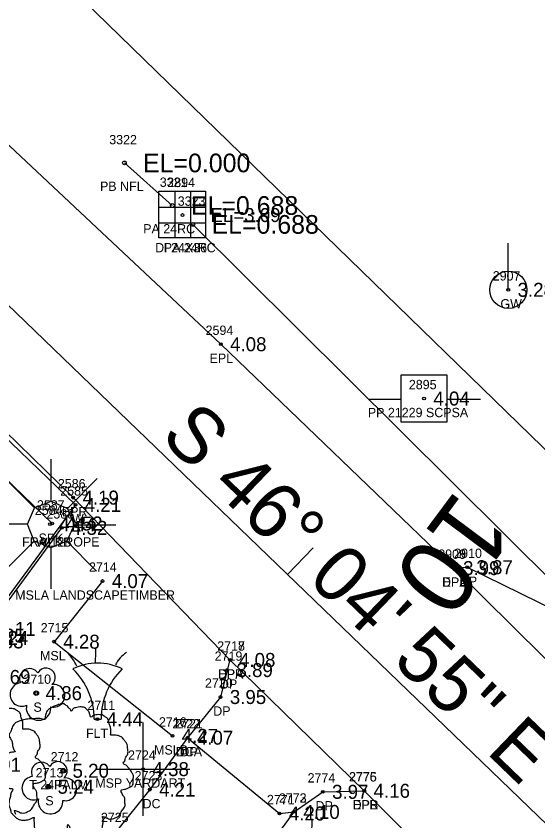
# Model space of a CAD drawing. Extents: x 2608598 to 2610682, y 641451 to 643526.
# Drawn here: x 2610142.2 to 2610198.2, y 642038.3 to 642124.7 of the extents above; entities that cross this region are included whole.
import ezdxf

# ---------------------------------------------------------------- set-up
doc = ezdxf.new("R2010")
doc.units = 0
for name, color, linetype in [('RD_EX_BldgApp', 7, 'Continuous'), ('RD_EX_BldgApp_txCode', 7, 'Continuous'), ('RD_EX_Conc', 7, 'Continuous'), ('RD_EX_Conc_txCode', 7, 'Continuous'), ('RD_EX_DR_Inlet', 7, 'Continuous'), ('RD_EX_DR_Inlet_txCode', 7, 'Continuous'), ('RD_EX_DR_Pipe', 7, 'Continuous'), ('RD_EX_DR_Pipe_txCode', 7, 'Continuous'), ('RD_EX_Driveway', 7, 'Continuous'), ('RD_EX_Driveway_txCode', 7, 'Continuous'), ('RD_EX_Fence_Other', 7, 'Continuous'), ('RD_EX_Fence_Other_txCode', 7, 'Continuous'), ('RD_EX_Misc', 7, 'Continuous'), ('RD_EX_Misc_txCode', 7, 'Continuous'), ('RD_EX_Road', 7, 'Continuous'), ('RD_EX_Road_txCode', 7, 'Continuous'), ('RD_EX_TX_BldgApp_ELEV', 7, 'Continuous'), ('RD_EX_TX_Conc_ELEV', 7, 'Continuous'), ('RD_EX_TX_DR_Inlet_ELEV', 7, 'Continuous'), ('RD_EX_TX_Driveway_ELEV', 7, 'Continuous'), ('RD_EX_TX_Fence_Other_ELEV', 7, 'Continuous'), ('RD_EX_TX_Misc_ELEV', 7, 'Continuous'), ('RD_EX_TX_Road_ELEV', 7, 'Continuous'), ('RD_EX_TX_UT_ELEV', 7, 'Continuous'), ('RD_EX_TX_VEG_ELEV', 7, 'Continuous'), ('RD_EX_UT', 7, 'Continuous'), ('RD_EX_UT_txCode', 7, 'Continuous'), ('RD_EX_VEG', 7, 'Continuous'), ('RD_EX_VEG_txCode', 7, 'Continuous'), ('RD_HC_Cl', 7, 'Continuous'), ('RD_HC_Data', 7, 'Continuous'), ('RD_HC_Data_Tic', 7, 'Continuous'), ('RD_HC_Survey_ELEV', 7, 'Continuous'), ('RD_HC_TX_Sta50', 7, 'Continuous'), ('RD_SMD_Locator', 7, 'Continuous'), ('RD_TX_Pipe_ElevEX', 7, 'Continuous')]:
    doc.layers.add(name, color=color, linetype=linetype)

msp = doc.modelspace()

# ---------------------------------------------------------------- linework, layer by layer
at = {"layer": 'RD_EX_BldgApp'}
for p, q in [((2610145.949, 642072.643), (2610145.949, 642077.152)), ((2610144.161, 642071.945), (2610140.978, 642075.127)), ((2610147.699, 642071.873), (2610150.895, 642075.069)), ((2610143.418, 642070.181), (2610138.896, 642070.181)), ((2610148.424, 642070.099), (2610152.92, 642070.099)), ((2610144.137, 642068.369), (2610141.019, 642065.251)), ((2610147.646, 642068.344), (2610150.837, 642065.153)), ((2610145.908, 642067.637), (2610145.908, 642063.227)), ((2610150.576, 642049.272), (2610151.326, 642049.272))]:
    msp.add_line(p, q, dxfattribs=at)
msp.add_lwpolyline([(2610134.705, 642085.572), (2610148.567, 642072.254), (2610138.223, 642058.218)], dxfattribs=at)
msp.add_lwpolyline([(2610144.161, 642071.945), (2610145.949, 642072.643), (2610147.699, 642071.873), (2610148.424, 642070.099), (2610147.646, 642068.344), (2610145.908, 642067.637), (2610144.137, 642068.369), (2610143.418, 642070.181)], close=True, dxfattribs=at)
for centre, radius, start, end in [((2610144.258, 642052.915), 4.895, 24.32791, 46.26654), ((2610112.869, 642056.61), 37.876, 358.06712, 0.27154), ((2610155.839, 642053.665), 3.283, 123.29064, 154.48862), ((2610150.951, 642049.272), 5.997, 63.77943, 116.22057), ((2610143.076, 642049.272), 7.5, 0, 45.83662), ((2610158.826, 642049.272), 7.5, 134.16338, 180), ((2610136.107, 642038.394), 37.876, 358.06712, 0.27154)]:
    msp.add_arc(centre, radius, start, end, dxfattribs=at)
at = {"layer": 'RD_EX_Conc'}
for points in [[(2610160.612, 642047.272), (2610156.554, 642041.695), (2610152.931, 642037.213), (2610150.731, 642035.233), (2610148.01, 642033.912), (2610141.177, 642033.459), (2610141.177, 642033.459), (2610137.988, 642033.476), (2610134.44, 642032.913), (2610131.048, 642029.279), (2610128.16, 642026.009), (2610122.885, 642018.814), (2610128.446, 642014.737), (2610133.488, 642011.041), (2610133.129, 642010.552)], [(2610097.632, 641937.698), (2610098.418, 641937.114), (2610146.498, 642001.846), (2610145.188, 642002.764), (2610160.492, 642023.462), (2610172.047, 642039.304)]]:
    msp.add_lwpolyline(points, dxfattribs=at)
at = {"layer": 'RD_EX_DR_Inlet'}
for p, q in [((2610159.228, 642105.905), (2610159.228, 642100.905)), ((2610160.928, 642105.905), (2610160.928, 642100.905)), ((2610157.528, 642104.205), (2610162.528, 642104.205)), ((2610157.528, 642102.505), (2610162.528, 642102.505))]:
    msp.add_line(p, q, dxfattribs=at)
msp.add_lwpolyline([(2610157.528, 642100.905), (2610157.528, 642105.905), (2610162.528, 642105.905), (2610162.528, 642100.905)], close=True, dxfattribs=at)
at = {"layer": 'RD_EX_DR_Pipe'}
for p, q in [((2610158.972, 642104.373), (2610153.828, 642108.939)), ((2610161.182, 642102.345), (2610218.859, 642045.058))]:
    msp.add_line(p, q, dxfattribs=at)
at = {"layer": 'RD_EX_Driveway'}
for points in [[(2610189.201, 642065.464), (2610190.633, 642065.558), (2610206.029, 642058.003), (2610212.058, 642057.248), (2610216.962, 642059.651), (2610226.196, 642070.204), (2610231.836, 642077.34), (2610253.985, 642109.297), (2610264.823, 642124.673)], [(2610165.14, 642055.61), (2610164.867, 642054.527), (2610164.148, 642051.634), (2610160.612, 642047.272), (2610170.483, 642039.135), (2610172.047, 642039.304), (2610175.131, 642041.462), (2610179.59, 642041.571)]]:
    msp.add_lwpolyline(points, dxfattribs=at)
at = {"layer": 'RD_EX_Fence_Other'}
for points in [[(2610132.58, 642142.761), (2610200.01, 642077.228), (2610202.789, 642080.045), (2610213.517, 642069.87), (2610210.469, 642066.294), (2610214.959, 642062.541)], [(2610147.084, 642069.782), (2610125.734, 642040.697), (2610098.694, 642003.858), (2610084.195, 641984.008), (2610080.523, 641986.54)]]:
    msp.add_lwpolyline(points, dxfattribs=at)
at = {"layer": 'RD_EX_Misc'}
for p, q in [((2610155.847, 642038.901), (2610155.847, 642048.901)), ((2610150.847, 642043.901), (2610160.847, 642043.901))]:
    msp.add_line(p, q, dxfattribs=at)
for points in [[(2610099.903, 642104.401), (2610102.737, 642104.088), (2610106.788, 642103.479), (2610109.503, 642102.419), (2610114.982, 642099.42), (2610118.245, 642096.797), (2610132.484, 642083.3), (2610146.063, 642070.249)], [(2610151.474, 642064.076), (2610146.269, 642057.572), (2610158.983, 642047.463)]]:
    msp.add_lwpolyline(points, dxfattribs=at)
at = {"layer": 'RD_EX_Road'}
for points in [[(2609576.606, 642656.063), (2609590.876, 642642.238), (2609605.189, 642628.776), (2609627.581, 642607.088), (2609646.03, 642589.107), (2609702.182, 642534.044), (2609780.351, 642458.947), (2609858.794, 642382.828), (2609938.323, 642306.422), (2610008.617, 642239.319), (2610086.297, 642162.544), (2610164.179, 642089.488), (2610189.201, 642065.464), (2610214.781, 642040.191), (2610225.859, 642030.159), (2610226.316, 642028.389), (2610235.43, 642019.753), (2610260.227, 641995.633), (2610272.389, 641983.247)], [(2609979.125, 642234.193), (2609992.401, 642221.664), (2610004.858, 642210.013), (2610027.001, 642188.802), (2610067.643, 642149.145), (2610070.798, 642146.186), (2610073.957, 642143.053), (2610116.512, 642103.007), (2610119.683, 642100.064), (2610135.088, 642085.919), (2610148.333, 642073.03), (2610165.14, 642055.61), (2610179.59, 642041.571), (2610196.49, 642024.706), (2610209.861, 642011.422), (2610228.388, 641994.056), (2610252.927, 641970.076), (2610256.351, 641966.743)]]:
    msp.add_lwpolyline(points, dxfattribs=at)
at = {"layer": 'RD_EX_UT'}
for p, q in [((2610195.056, 642095.325), (2610195.056, 642100.325)), ((2610188.498, 642086.169), (2610183.498, 642086.169)), ((2610183.498, 642086.169), (2610183.498, 642081.169)), ((2610188.498, 642081.169), (2610188.498, 642086.169)), ((2610180.067, 642083.606), (2610183.536, 642083.606)), ((2610188.427, 642083.606), (2610192.067, 642083.606)), ((2610183.498, 642081.169), (2610188.498, 642081.169))]:
    msp.add_line(p, q, dxfattribs=at)
msp.add_circle((2610195.056, 642095.325), 1.999, dxfattribs=at)
at = {"layer": 'RD_EX_VEG'}
for centre, radius in [((2610144.364, 642052.049), 0.25), ((2610147.256, 642043.722), 0.25), ((2610147.244, 642043.703), 0.0001), ((2610145.642, 642042.006), 0.25)]:
    msp.add_circle(centre, radius, dxfattribs=at)
for centre, radius, start, end in [((2610143.643, 642053.596), 1.084, 34.97629, 204.75602), ((2610145.409, 642053.751), 0.995, 308.76261, 152.04674), ((2610142.8, 642051.893), 1.257, 96.45179, 294.73401), ((2610146.204, 642051.77), 1.218, 256.56668, 98.10463), ((2610144.609, 642050.453), 1.318, 166.88266, 5.75893), ((2610144.921, 642043.553), 1.084, 34.97629, 204.75602), ((2610146.687, 642043.708), 0.995, 308.76261, 152.04674), ((2610144.078, 642041.85), 1.257, 96.45179, 294.73401), ((2610147.482, 642041.727), 1.218, 256.56668, 98.10463), ((2610145.888, 642040.41), 1.318, 166.88266, 5.75893)]:
    msp.add_arc(centre, radius, start, end, dxfattribs=at)
for points in [[(2610142.172, 642039.041), (2610142.097, 642039.216), (2610142.047, 642039.466), (2610142.122, 642039.441), (2610142.297, 642039.391), (2610142.572, 642039.266), (2610142.797, 642039.191), (2610143.121, 642039.216), (2610143.396, 642039.316), (2610143.846, 642039.591), (2610144.121, 642040.066), (2610144.396, 642040.466), (2610144.471, 642040.791), (2610144.421, 642041.016), (2610144.396, 642041.515), (2610144.196, 642041.765), (2610144.146, 642041.89), (2610144.046, 642042.29), (2610144.121, 642042.34), (2610144.396, 642042.39), (2610144.771, 642042.515), (2610145.046, 642042.64), (2610145.271, 642042.815), (2610145.345, 642043.04), (2610145.321, 642043.439), (2610145.37, 642043.839), (2610145.296, 642043.989), (2610145.196, 642044.139), (2610145.121, 642044.339), (2610144.971, 642044.489), (2610144.871, 642044.639), (2610144.771, 642044.739), (2610144.646, 642044.889), (2610144.471, 642045.014), (2610144.321, 642045.064), (2610144.271, 642045.214), (2610144.421, 642045.414), (2610144.471, 642045.514), (2610144.496, 642045.738), (2610144.721, 642046.088), (2610144.771, 642046.488), (2610144.721, 642046.913), (2610144.671, 642047.188), (2610144.521, 642047.463), (2610144.321, 642047.713), (2610144.196, 642047.888), (2610144.021, 642048.012), (2610143.696, 642048.137), (2610143.446, 642048.187), (2610143.096, 642048.187), (2610142.897, 642048.237), (2610142.922, 642048.287), (2610142.922, 642048.437), (2610142.922, 642048.712), (2610142.847, 642049.162), (2610142.697, 642049.662), (2610142.697, 642049.687), (2610142.597, 642049.937), (2610142.372, 642050.137), (2610142.197, 642050.236), (2610141.997, 642050.361), (2610141.747, 642050.386), (2610141.447, 642050.386), (2610141.172, 642050.336), (2610140.972, 642050.236), (2610140.797, 642050.112), (2610140.722, 642050.261), (2610140.623, 642050.561), (2610140.573, 642050.711), (2610140.423, 642050.886), (2610140.198, 642051.086), (2610139.748, 642051.211), (2610139.123, 642051.136), (2610138.823, 642050.936), (2610138.673, 642050.761), (2610138.623, 642050.886), (2610138.423, 642051.086), (2610138.324, 642051.261), (2610138.149, 642051.386), (2610137.999, 642051.486), (2610137.899, 642051.536)], [(2610147.388, 642050.889), (2610147.088, 642050.914), (2610146.764, 642050.814), (2610146.514, 642050.715), (2610146.289, 642050.64), (2610146.064, 642050.54), (2610145.764, 642050.365), (2610145.539, 642050.165), (2610145.414, 642049.915), (2610145.364, 642049.69), (2610145.314, 642049.415), (2610145.314, 642049.24), (2610145.189, 642049.215), (2610145.039, 642049.24), (2610144.789, 642049.315), (2610144.539, 642049.315), (2610144.29, 642049.315), (2610143.94, 642049.29), (2610143.59, 642049.29), (2610143.315, 642049.24), (2610142.99, 642049.19), (2610142.615, 642049.065), (2610142.265, 642048.94), (2610141.966, 642048.69), (2610141.716, 642048.216), (2610141.591, 642047.866), (2610141.441, 642047.616), (2610141.591, 642047.166), (2610141.766, 642046.816), (2610141.791, 642046.616), (2610141.866, 642046.192), (2610141.966, 642045.967), (2610142.091, 642045.767), (2610142.016, 642045.742), (2610141.641, 642045.692), (2610141.341, 642045.592), (2610140.916, 642045.367), (2610140.691, 642045.142), (2610140.591, 642044.817), (2610140.566, 642044.467), (2610140.466, 642044.267), (2610140.391, 642043.992), (2610140.366, 642043.917), (2610140.316, 642043.593), (2610140.416, 642043.143), (2610140.441, 642042.793), (2610140.566, 642042.568), (2610140.716, 642042.393), (2610140.891, 642042.143), (2610141.291, 642041.918), (2610141.616, 642041.818), (2610141.816, 642041.793), (2610141.641, 642041.294), (2610141.591, 642040.944), (2610141.466, 642040.544), (2610141.466, 642040.469), (2610141.416, 642039.994), (2610141.566, 642039.669), (2610141.641, 642039.295), (2610141.816, 642039.07), (2610142.091, 642038.77), (2610142.415, 642038.545), (2610142.915, 642038.42), (2610143.315, 642038.445), (2610143.89, 642038.62), (2610144.14, 642038.695), (2610144.115, 642038.52), (2610144.14, 642038.145), (2610144.14, 642037.72), (2610144.29, 642037.395), (2610144.39, 642037.12), (2610144.539, 642036.871), (2610144.864, 642036.646), (2610145.264, 642036.571), (2610145.689, 642036.421), (2610146.139, 642036.346), (2610146.639, 642036.321), (2610147.238, 642036.471), (2610147.513, 642036.596), (2610147.613, 642036.771), (2610147.813, 642037.145), (2610147.763, 642037.37), (2610147.788, 642037.97), (2610147.888, 642037.795), (2610148.063, 642037.445), (2610148.563, 642037.145), (2610148.963, 642036.971), (2610149.437, 642036.821), (2610149.737, 642036.746), (2610150.212, 642036.821), (2610150.587, 642036.896), (2610150.962, 642037.021), (2610151.262, 642037.295), (2610151.436, 642037.57), (2610151.486, 642037.845), (2610151.561, 642038.22), (2610151.611, 642038.395)], [(2610151.611, 642038.395), (2610151.536, 642038.57), (2610151.486, 642038.82), (2610151.561, 642038.795), (2610151.736, 642038.745), (2610152.011, 642038.62), (2610152.236, 642038.545), (2610152.561, 642038.57), (2610152.836, 642038.67), (2610153.286, 642038.945), (2610153.561, 642039.419), (2610153.835, 642039.819), (2610153.91, 642040.144), (2610153.86, 642040.369), (2610153.835, 642040.869), (2610153.635, 642041.119), (2610153.585, 642041.244), (2610153.486, 642041.643), (2610153.561, 642041.693), (2610153.835, 642041.743), (2610154.21, 642041.868), (2610154.485, 642041.993), (2610154.71, 642042.168), (2610154.785, 642042.393), (2610154.76, 642042.793), (2610154.81, 642043.193), (2610154.735, 642043.343), (2610154.635, 642043.493), (2610154.56, 642043.693), (2610154.41, 642043.842), (2610154.31, 642043.992), (2610154.21, 642044.092), (2610154.085, 642044.242), (2610153.91, 642044.367), (2610153.76, 642044.417), (2610153.71, 642044.567), (2610153.86, 642044.767), (2610153.91, 642044.867), (2610153.935, 642045.092), (2610154.16, 642045.442), (2610154.21, 642045.842), (2610154.16, 642046.266), (2610154.11, 642046.541), (2610153.96, 642046.816), (2610153.76, 642047.066), (2610153.635, 642047.241), (2610153.461, 642047.366), (2610153.136, 642047.491), (2610152.886, 642047.541), (2610152.536, 642047.541), (2610152.336, 642047.591), (2610152.361, 642047.641), (2610152.361, 642047.791), (2610152.361, 642048.066), (2610152.286, 642048.515), (2610152.136, 642049.015), (2610152.136, 642049.04), (2610152.036, 642049.29), (2610151.811, 642049.49), (2610151.636, 642049.59), (2610151.436, 642049.715), (2610151.187, 642049.74), (2610150.887, 642049.74), (2610150.612, 642049.69), (2610150.412, 642049.59), (2610150.237, 642049.465), (2610150.162, 642049.615), (2610150.062, 642049.915), (2610150.012, 642050.065), (2610149.862, 642050.24), (2610149.637, 642050.44), (2610149.187, 642050.565), (2610148.563, 642050.49), (2610148.263, 642050.29), (2610148.113, 642050.115), (2610148.063, 642050.24), (2610147.863, 642050.44), (2610147.763, 642050.615), (2610147.588, 642050.74), (2610147.438, 642050.839), (2610147.338, 642050.889)]]:
    msp.add_spline(points, degree=3, dxfattribs=at)
at = {"layer": 'RD_HC_Cl'}
msp.add_line((2610092.394, 642140.787), (2610263.672, 641975.859), dxfattribs=at)
at = {"layer": 'RD_HC_Data_Tic'}
msp.add_line((2610171.341, 642064.767), (2610174.115, 642067.648), dxfattribs=at)
at = {"layer": 'RD_SMD_Locator'}
for centre, radius in [((2610153.828, 642108.939), 0.2), ((2610158.972, 642104.373), 0.2), ((2610160.066, 642103.347), 0.15), ((2610161.182, 642102.345), 0.2), ((2610195.056, 642095.325), 0.15), ((2610164.179, 642089.488), 0.15), ((2610186.007, 642083.66), 0.15), ((2610148.333, 642073.03), 0.15), ((2610148.567, 642072.254), 0.15), ((2610145.835, 642070.178), 0.15), ((2610146.063, 642070.249), 0.15), ((2610147.084, 642069.782), 0.15), ((2610189.201, 642065.464), 0.15), ((2610189.201, 642065.464), 0.15), ((2610190.633, 642065.558), 0.15), ((2610151.474, 642064.076), 0.15), ((2610146.269, 642057.572), 0.15), ((2610165.14, 642055.61), 0.15), ((2610165.14, 642055.61), 0.15), ((2610164.867, 642054.527), 0.15), ((2610144.364, 642052.049), 0.15), ((2610164.148, 642051.634), 0.15), ((2610150.923, 642049.254), 0.15), ((2610158.983, 642047.463), 0.15), ((2610160.612, 642047.272), 0.15), ((2610160.612, 642047.272), 0.15), ((2610155.847, 642043.901), 0.15), ((2610147.256, 642043.722), 0.15), ((2610145.642, 642042.006), 0.15), ((2610156.554, 642041.695), 0.15), ((2610175.131, 642041.462), 0.15), ((2610179.59, 642041.571), 0.15), ((2610179.59, 642041.571), 0.15), ((2610170.483, 642039.135), 0.15), ((2610172.047, 642039.304), 0.15), ((2610172.047, 642039.304), 0.15)]:
    msp.add_circle(centre, radius, dxfattribs=at)

# ---------------------------------------------------------------- texts
at = {"layer": 'RD_EX_BldgApp_txCode'}
for s, p in [('2584', (2610144.205, 642071.178)), ('SPK', (2610144.606, 642068.178)), ('2711', (2610149.86, 642050.254)), ('FLT', (2610149.702, 642047.254))]:
    msp.add_text(s, height=1, dxfattribs=at).set_placement(p)
at = {"layer": 'RD_EX_Conc_txCode'}
for s, p in [('2722', (2610158.982, 642048.272)), ('DCA', (2610159.345, 642045.272)), ('2723', (2610154.924, 642042.695)), ('DC', (2610155.774, 642039.695)), ('2772', (2610170.417, 642040.304)), ('2725', (2610151.301, 642038.213))]:
    msp.add_text(s, height=1, dxfattribs=at).set_placement(p)
at = {"layer": 'RD_EX_DR_Inlet_txCode'}
for s, p in [('2894', (2610158.436, 642106.347)), ('DI 24X36', (2610157.129, 642099.347))]:
    msp.add_text(s, height=1, dxfattribs=at).set_placement(p)
at = {"layer": 'RD_EX_DR_Pipe_txCode'}
for s, p in [('3322', (2610152.198, 642110.939)), ('3321', (2610157.625, 642106.373)), ('PB NFL', (2610151.206, 642105.939)), ('3323', (2610159.552, 642104.345)), ('PA 24RC', (2610155.846, 642101.373)), ('PA 24RC', (2610158.056, 642099.345))]:
    msp.add_text(s, height=1, dxfattribs=at).set_placement(p)
at = {"layer": 'RD_EX_Driveway_txCode'}
for s, p in [('2909', (2610187.531, 642066.464)), ('2910', (2610189.247, 642066.558)), ('DPA', (2610187.933, 642063.464)), ('DP', (2610189.853, 642063.558)), ('2718', (2610163.794, 642056.61)), ('2719', (2610163.52, 642055.527)), ('DPA', (2610163.873, 642053.61)), ('2720', (2610162.478, 642052.634)), ('DP', (2610164.087, 642052.527)), ('DP', (2610163.368, 642049.634)), ('2721', (2610159.266, 642048.272)), ('DP', (2610159.833, 642045.272)), ('2774', (2610173.501, 642042.462)), ('2775', (2610177.96, 642042.571)), ('2771', (2610169.136, 642040.135)), ('2773', (2610170.417, 642040.304)), ('DPB', (2610178.338, 642039.571)), ('DP', (2610174.352, 642039.462))]:
    msp.add_text(s, height=1, dxfattribs=at).set_placement(p)
at = {"layer": 'RD_EX_Fence_Other_txCode'}
for s, p in [('2588', (2610145.454, 642070.782)), ('FRA 12ROPE', (2610142.836, 642067.782))]:
    msp.add_text(s, height=1, dxfattribs=at).set_placement(p)
at = {"layer": 'RD_EX_Misc_txCode'}
for s, p in [('2585', (2610146.937, 642073.254)), ('2587', (2610144.433, 642071.749)), ('W', (2610148.197, 642070.254)), ('WLKB', (2610144.323, 642067.749)), ('2714', (2610150.022, 642065.076)), ('MSLA LANDSCAPETIMBER', (2610142.095, 642062.076)), ('2715', (2610144.84, 642058.572)), ('MSL', (2610144.766, 642055.572)), ('2716', (2610157.534, 642048.463)), ('2724', (2610154.217, 642044.901)), ('MSLB', (2610157.013, 642045.463)), ('MSP YARDART', (2610150.697, 642041.901))]:
    msp.add_text(s, height=1, dxfattribs=at).set_placement(p)
at = {"layer": 'RD_EX_Road_txCode'}
for s, p in [('2594', (2610162.549, 642090.488)), ('EPL', (2610162.974, 642087.488)), ('2586', (2610146.68, 642074.03)), ('EPR', (2610147.105, 642071.03)), ('2908', (2610187.531, 642066.464)), ('EPL', (2610187.996, 642063.464)), ('2717', (2610163.794, 642056.61)), ('EPR', (2610163.912, 642053.61)), ('2776', (2610177.937, 642042.571)), ('EPR', (2610178.362, 642039.571))]:
    msp.add_text(s, height=1, dxfattribs=at).set_placement(p)
at = {"layer": 'RD_EX_TX_BldgApp_ELEV'}
for s, p in [('4.44', (2610146.835, 642069.428)), ('4.69', (2610139.833, 642053.04)), ('4.44', (2610151.923, 642048.504))]:
    msp.add_text(s, height=1.5, dxfattribs=at).set_placement(p)
at = {"layer": 'RD_EX_TX_Conc_ELEV'}
for s, p in [('4.07', (2610161.612, 642046.522)), ('4.21', (2610157.554, 642040.945)), ('4.10', (2610173.047, 642038.554))]:
    msp.add_text(s, height=1.5, dxfattribs=at).set_placement(p)
at = {"layer": 'RD_EX_TX_DR_Inlet_ELEV'}
msp.add_text('EL=3.09', height=1.5, dxfattribs=at).set_placement((2610163.066, 642102.597))
at = {"layer": 'RD_EX_TX_Driveway_ELEV'}
for s, p in [('3.99', (2610190.201, 642064.714)), ('3.87', (2610191.633, 642064.808)), ('4.08', (2610166.14, 642054.86)), ('3.89', (2610165.867, 642053.777)), ('3.95', (2610165.148, 642050.884)), ('4.07', (2610161.612, 642046.522)), ('3.97', (2610176.131, 642040.712)), ('4.16', (2610180.59, 642040.821)), ('4.20', (2610171.483, 642038.385)), ('4.10', (2610173.047, 642038.554))]:
    msp.add_text(s, height=1.5, dxfattribs=at).set_placement(p)
at = {"layer": 'RD_EX_TX_Fence_Other_ELEV'}
msp.add_text('4.32', height=1.5, dxfattribs=at).set_placement((2610148.084, 642069.032))
at = {"layer": 'RD_EX_TX_Misc_ELEV'}
for s, p in [('4.21', (2610149.567, 642071.504)), ('4.52', (2610147.563, 642069.499)), ('4.07', (2610152.474, 642063.326)), ('4.25', (2610139.223, 642057.468)), ('4.33', (2610139.092, 642056.852)), ('4.28', (2610147.269, 642056.822)), ('4.27', (2610159.983, 642046.713)), ('4.38', (2610156.847, 642043.151))]:
    msp.add_text(s, height=1.5, dxfattribs=at).set_placement(p)
at = {"layer": 'RD_EX_TX_Road_ELEV'}
for s, p in [('4.08', (2610165.179, 642088.738)), ('4.19', (2610149.333, 642072.28)), ('3.99', (2610190.201, 642064.714)), ('4.08', (2610166.14, 642054.86)), ('4.16', (2610180.59, 642040.821))]:
    msp.add_text(s, height=1.5, dxfattribs=at).set_placement(p)
at = {"layer": 'RD_EX_TX_UT_ELEV'}
for s, p in [('3.28', (2610196.056, 642094.575)), ('4.11', (2610140.393, 642058.19)), ('4.24', (2610139.594, 642057.22))]:
    msp.add_text(s, height=1.5, dxfattribs=at).set_placement(p)
at = {"layer": 'RD_EX_TX_VEG_ELEV'}
for s, p in [('4.86', (2610145.364, 642051.299)), ('4.91', (2610138.817, 642043.619)), ('5.20', (2610148.256, 642042.972)), ('5.24', (2610146.642, 642041.256))]:
    msp.add_text(s, height=1.5, dxfattribs=at).set_placement(p)
at = {"layer": 'RD_EX_UT_txCode'}
for s, p in [('2907', (2610193.386, 642096.325)), ('GW', (2610194.213, 642093.325)), ('2895', (2610184.377, 642084.66)), ('PP 21229 SCPSA', (2610179.968, 642081.66))]:
    msp.add_text(s, height=1, dxfattribs=at).set_placement(p)
at = {"layer": 'RD_EX_VEG_txCode'}
for s, p in [('2710', (2610142.978, 642053.049)), ('S', (2610144.057, 642050.049)), ('2712', (2610145.91, 642044.722)), ('2713', (2610144.296, 642043.006)), ('T 24PALM', (2610143.603, 642041.722)), ('S', (2610145.335, 642040.006))]:
    msp.add_text(s, height=1, dxfattribs=at).set_placement(p)
at = {"layer": 'RD_HC_Data'}
msp.add_text('S 46%%d 04\' 55" E', height=6, rotation=316.08195, dxfattribs=at).set_placement((2610157.542, 642079.442))
at = {"layer": 'RD_HC_Survey_ELEV'}
msp.add_text('4.04', height=1.5, dxfattribs=at).set_placement((2610187.007, 642082.91))
at = {"layer": 'RD_HC_TX_Sta50'}
msp.add_text('10', height=8, rotation=233.30287, dxfattribs=at).set_placement((2610189.533, 642074.076))
at = {"layer": 'RD_TX_Pipe_ElevEX'}
for s, p in [('EL=0.000', (2610155.828, 642107.939)), ('EL=0.688', (2610160.972, 642103.373)), ('EL=0.688', (2610163.182, 642101.345))]:
    msp.add_text(s, height=2, dxfattribs=at).set_placement(p)

doc.saveas('drawing.dxf')
